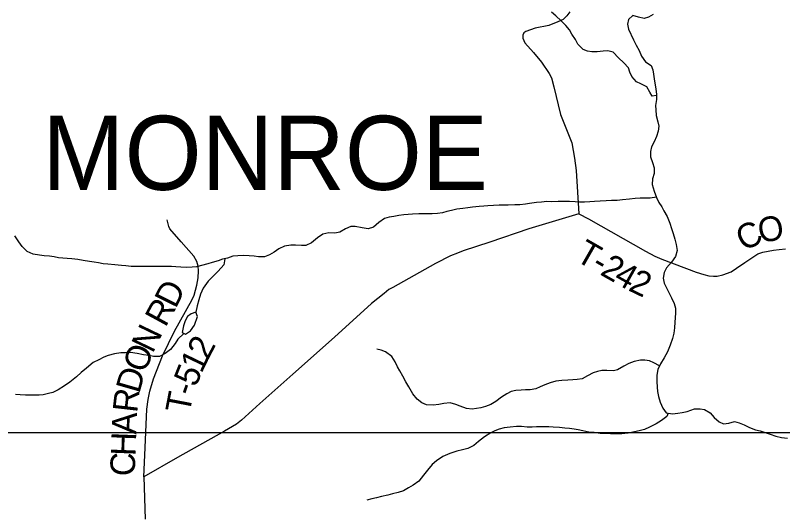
# Model space of a CAD drawing. Extents: x 1759416 to 2214760, y 252598 to 1116833.
# Drawn here: x 1993486 to 2002804, y 879430 to 885483 of the extents above; entities that cross this region are included whole.
import ezdxf

# ---------------------------------------------------------------- set-up
doc = ezdxf.new("R2010")
doc.units = 0
for name, color, linetype in [('GM_X_County_Road', 7, 'Continuous'), ('GM_X_Minor_Lake', 7, 'Continuous'), ('GM_X_Minor_River', 7, 'Continuous'), ('GM_X_Township_Road', 7, 'Continuous'), ('GM_X_Township_Road_Text', 7, 'Continuous'), ('GM_X_Township_Text', 7, 'Continuous'), ('SC_Scratch1', 7, 'Continuous')]:
    doc.layers.add(name, color=color, linetype=linetype)

msp = doc.modelspace()

# ---------------------------------------------------------------- linework, layer by layer
at = {"layer": 'GM_X_County_Road'}
msp.add_lwpolyline([(2000217.9, 885523.9), (2000183.9, 885475.9), (2000139.8, 885433.9), (2000073.7, 885403.9), (1999963.6, 885360), (1999797.5, 885326.1), (1999683.3, 885286.1), (1999661.3, 885270.1), (1999647.3, 885242.1), (1999647.2, 885206.1), (1999671.2, 885150), (1999779.1, 885031.7), (1999877, 884915.4), (1999969, 884777.1), (1999994.9, 884723.1), (2000026.8, 884612.9), (2000106.5, 884276.3), (2000242.6, 883936.1), (2000277.2, 883748.6), (2000296.4, 883600), (2000328.2, 883073), (1999721.7, 882889.1), (1999248.2, 882729.1), (1998923.9, 882623.2), (1998853.8, 882595.3), (1998769.7, 882561.3), (1998587.5, 882467.4), (1998070.8, 882175.5), (1998020.8, 882151.5), (1997964.7, 882105.5), (1997812.5, 881981.5), (1997359.7, 881573.4), (1996856.9, 881125.2), (1996454.3, 880767.2), (1996231.9, 880565.1), (1996169.8, 880519.1), (1996027.6, 880433.1), (1995456.9, 880113.3), (1995048.4, 879877.3), (1995061.1, 879363)], dxfattribs=at)
at = {"layer": 'GM_X_Minor_Lake'}
for points in [[(1995679.1, 881876.8), (1995622.9, 881857.1), (1995574.7, 881823.4), (1995550.3, 881771.5), (1995529.9, 881711.5), (1995513.4, 881629.5), (1995551.3, 881609.2), (1995611.6, 881648.9), (1995662.1, 881718.7), (1995698.8, 881824.6)], [(1995698.8, 881824.6), (1995679.1, 881876.8)]]:
    msp.add_lwpolyline(points, dxfattribs=at)
at = {"layer": 'GM_X_Minor_River'}
for points in [[(2001271.2, 884507.4), (2001219.1, 884499.7), (2001191.4, 884550), (2001155.7, 884612.3), (2001081.9, 884648.8), (2001030, 884673.2), (2000972.4, 884739.7), (2000948.7, 884793.9), (2000931, 884844.1), (2000873.3, 884906.6), (2000811.7, 884967.1), (2000746, 885035.6), (2000680.1, 885052), (2000624, 885046.4), (2000551.9, 885038.8), (2000487.8, 885039.2), (2000431.8, 885045.6), (2000379.9, 885068), (2000318.3, 885134.5), (2000286.6, 885188.8), (2000245, 885255.1), (2000213.3, 885307.4), (2000169.6, 885359.8), (2000115.9, 885416.2), (2000050.2, 885476.8), (1999998.4, 885521.2)], [(2001229.4, 885493.2), (2001175.1, 885459.5), (2001123, 885445.9), (2001053.1, 885462.3), (2000985.1, 885480.8), (2000930.7, 885433.1), (2000920.4, 885375), (2000930, 885314.9), (2000993.2, 885186.3), (2001024.9, 885121.9), (2001062.5, 885053.6), (2001090.1, 884985.3), (2001137.7, 884918.9), (2001205.5, 884874.4), (2001225.1, 884822.2), (2001236.8, 884768), (2001244.5, 884711.9), (2001250.1, 884659.8), (2001261.7, 884591.6), (2001271.3, 884519.4), (2001270.9, 884459.3), (2001258.4, 884387.3), (2001262.1, 884335.2), (2001267.6, 884267)], [(2001267.6, 884267), (2001287.2, 884188.8), (2001298.8, 884136.6), (2001292.5, 884076.5), (2001270, 884012.6), (2001243.6, 883944.6), (2001211.2, 883884.8), (2001196.8, 883830.8), (2001200.4, 883764.6), (2001222, 883696.4), (2001243.6, 883630.1), (2001243.1, 883560), (2001224.7, 883496), (2001220.3, 883427.9), (2001241.8, 883345.7), (2001273.3, 883271.4), (2001299, 883211.1), (2001334.7, 883158.8), (2001362.3, 883106.5), (2001402, 883038.2), (2001435.5, 882959.8), (2001455.1, 882895.6), (2001472.7, 882831.4), (2001494.3, 882763.1), (2001511.9, 882700.9), (2001523.4, 882626.7), (2001501, 882552.7), (2001452.5, 882482.9), (2001394, 882415.2), (2001365.6, 882361.3), (2001351.1, 882289.3), (2001362.8, 882231.1), (2001396.4, 882164.8), (2001426, 882106.5), (2001455.7, 882050.2), (2001487.3, 881981.9), (2001503, 881925.7), (2001502.6, 881869.6), (2001498.2, 881809.6), (2001495.9, 881755.5), (2001489.4, 881685.4), (2001481, 881621.4), (2001466.6, 881557.4), (2001438.1, 881477.4), (2001403.5, 881397.5), (2001363, 881323.7), (2001320.5, 881249.8), (2001286, 881179.9), (2001277.6, 881111.9), (2001275.1, 881035.8), (2001280.7, 880967.6), (2001284.3, 880913.5), (2001294, 880853.3), (2001317.5, 880785.1), (2001347.1, 880712.8), (2001390.8, 880656.4), (2001466.8, 880641.9), (2001530.9, 880649.5), (2001585, 880659.2), (2001643.1, 880672.8), (2001733.4, 880702.3), (2001801.5, 880703.9), (2001855.5, 880693.5), (2001923.3, 880653), (2001971, 880596.6), (2002030.7, 880546.1), (2002084.6, 880519.8), (2002150.7, 880529.3), (2002216.9, 880551), (2002276.8, 880532.5), (2002336.8, 880508.1), (2002402.6, 880475.7), (2002474.5, 880449.2), (2002530.5, 880434.8), (2002650.3, 880393.9), (2002720.2, 880371.5), (2002790.2, 880357), (2002864.2, 880346.5)], [(2001272.7, 883272.9), (2001195.2, 883261.8), (2001127.1, 883262.3), (2001075, 883260.6), (2001013, 883257), (2000944.9, 883249.4), (2000858.7, 883241.9), (2000792.6, 883234.4), (2000726.5, 883232.8), (2000658.5, 883229.2), (2000588.4, 883225.7), (2000520.3, 883220.1), (2000460.2, 883216.5), (2000398.1, 883214.8), (2000336.1, 883215.2), (2000282, 883215.6), (2000214, 883220), (2000147.9, 883222.5), (2000075.9, 883222.9), (2000001.8, 883219.4), (1999941.7, 883219.8), (1999875.6, 883214.2), (1999813.5, 883208.6), (1999731.4, 883197.1), (1999681.3, 883189.4), (1999613.2, 883181.8), (1999553.1, 883180.2), (1999471, 883176.7), (1999414.9, 883177.1), (1999360.9, 883175.4), (1999292.8, 883173.8), (1999224.7, 883170.3), (1999174.6, 883166.6), (1999116.6, 883162.9), (1999036.4, 883153.4), (1998982.3, 883145.8), (1998918.2, 883138.2), (1998846.1, 883126.6), (1998781.9, 883113), (1998725.8, 883101.3), (1998671.6, 883085.7), (1998611.5, 883076), (1998547.4, 883072.4), (1998459.4, 883071), (1998387.3, 883071.5), (1998307.2, 883068), (1998257.1, 883064.3), (1998205, 883058.6), (1998140.9, 883051), (1998080.8, 883041.4), (1998026.7, 883031.7), (1997968.5, 883016), (1997898.2, 882968.4), (1997833.7, 882910.7), (1997771.5, 882889.1), (1997695.6, 882901.6), (1997613.6, 882918.2), (1997559.5, 882916.5), (1997495.3, 882888.9), (1997427, 882847.2), (1997364.8, 882837.6), (1997294.8, 882842.1), (1997220.6, 882826.5), (1997154.3, 882780.9), (1997083.8, 882721.2), (1997015.5, 882685.6), (1996959.5, 882685.9), (1996887.4, 882690.4), (1996831.4, 882690.8), (1996753.2, 882679.2), (1996687, 882645.6), (1996628.7, 882605.9), (1996572.4, 882572.2), (1996512.2, 882550.6), (1996440.1, 882549), (1996388.1, 882557.4), (1996324.1, 882561.8), (1996256, 882564.2), (1996188, 882562.7), (1996127.9, 882557), (1996061.7, 882535.4), (1996003.5, 882519.8), (1995947.3, 882500.1), (1995877.2, 882480.5), (1995823, 882462.8), (1995686.6, 882429.7), (1995634.6, 882424), (1995562.5, 882418.4), (1995496.4, 882422.9), (1995436.4, 882427.2), (1995380.4, 882431.6), (1995324.3, 882434), (1995266.3, 882430.3), (1995208.2, 882430.7), (1995158.2, 882433), (1995092.1, 882431.4), (1994893.9, 882432.7), (1994825.9, 882439.2), (1994775.9, 882443.5), (1994693.8, 882452), (1994607.8, 882458.6)], [(1994607.8, 882458.6), (1994551.8, 882465), (1994497.8, 882475.3), (1994441.8, 882483.7), (1994387.8, 882492), (1994307.8, 882506.6), (1994243.8, 882517), (1994171.8, 882523.5), (1994115.8, 882527.8), (1994061.8, 882534.2), (1994011.7, 882538.5), (1993957.8, 882548.9), (1993899.8, 882557.3), (1993835.7, 882563.7), (1993777.7, 882570.1), (1993703.7, 882582.6), (1993629.9, 882613.1), (1993568.2, 882675.6), (1993528.5, 882729.9), (1993480.9, 882804.3)], [(1996028.4, 882526.5), (1996017.1, 882453.6), (1995950.6, 882375.9), (1995827.7, 882254.5), (1995765.1, 882170.7), (1995732.6, 882096.8), (1995716.1, 882028.8), (1995695.6, 881952.8), (1995679.1, 881876.8)], [(1995533, 881619), (1995460.8, 881547.7), (1995426.5, 881495.8), (1995370, 881424), (1995305.6, 881376.4), (1995237.3, 881338.8), (1995165.2, 881339.2), (1995111.2, 881349.6), (1995041.2, 881360), (1994965.3, 881374.6), (1994883.3, 881387.1), (1994825.2, 881385.5), (1994765.1, 881381.8), (1994691, 881370.3), (1994612.8, 881350.8), (1994562.6, 881329.1), (1994500.3, 881299.4), (1994432.1, 881265.8), (1994351.5, 881196.2), (1994287.2, 881146.5), (1994226.8, 881090.8), (1994148.3, 881029.2), (1994083.9, 880981.5), (1994007.6, 880936), (1993941.3, 880902.3), (1993889.1, 880888.6), (1993825, 880875), (1993774.9, 880871.3), (1993718.9, 880869.7), (1993662.8, 880870.1), (1993610.8, 880870.4), (1993544.7, 880874.8), (1993488.7, 880877.2)], [(2001308.4, 881225.3), (2001240.5, 881262.3), (2001188.6, 881286.7), (2001130.6, 881295.1), (2001076.5, 881293.4), (2001000.4, 881277.9), (2000936.1, 881252.3), (2000873.9, 881220.6), (2000799.5, 881179), (2000749.4, 881165.3), (2000669.4, 881167.8), (2000609.3, 881170.2), (2000553.2, 881156.6), (2000503, 881138.8), (2000434.7, 881103.2), (2000368.5, 881069.6), (2000310.3, 881057.9), (2000254.2, 881054.3), (2000194.2, 881050.7), (2000122.1, 881049.1), (2000048, 881039.6), (1999979.8, 881020), (1999915.5, 880994.4), (1999859.3, 880970.7), (1999807.1, 880945), (1999737, 880933.4), (1999682.9, 880933.8), (1999628.9, 880930.1), (1999564.8, 880926.5), (1999508.6, 880912.8), (1999454.4, 880885.1), (1999390.1, 880845.5), (1999321.7, 880791.8), (1999261.4, 880758.2), (1999193.2, 880730.5), (1999139, 880716.9), (1999086.9, 880707.2), (1999032.8, 880701.5), (1998964.8, 880706), (1998888.9, 880734.5), (1998835, 880756.9), (1998767.1, 880775.3), (1998688.9, 880767.8), (1998628.8, 880756.2), (1998558.7, 880748.6), (1998480.6, 880753.1), (1998422.7, 880775.5), (1998365, 880822), (1998311.3, 880884.4), (1998263.8, 880968.9), (1998226.2, 881033.2), (1998190.6, 881101.5), (1998156.9, 881163.9), (1998127.2, 881214.1), (1998097.6, 881274.4), (1998056, 881340.8), (1997982.3, 881397.3), (1997926.3, 881415.7), (1997874.4, 881430.1)], [(2001412.7, 880652.2), (2001398.5, 880610.3), (2001332.1, 880562.6), (2001267.8, 880523), (2001187.5, 880479.4), (2001125.3, 880453.8), (2001063.1, 880436.2), (2001004.9, 880422.5), (2000926.8, 880407), (2000850.7, 880401.4), (2000764.6, 880400), (2000714.5, 880398.3), (2000644.5, 880402.8), (2000588.4, 880405.1), (2000514.4, 880415.6), (2000450.4, 880422), (2000378.4, 880436.5), (2000322.4, 880446.9), (2000270.4, 880455.2), (2000216.5, 880463.6), (2000160.4, 880470), (2000092.4, 880478.4), (2000018.4, 880482.9), (1999964.3, 880483.2), (1999886.3, 880485.7), (1999816.2, 880484.2), (1999760.1, 880480.5), (1999702.1, 880478.9), (1999632, 880487.3), (1999572, 880487.7), (1999495.9, 880482.2), (1999423.8, 880472.7), (1999359.6, 880455), (1999309.4, 880437.3), (1999259.2, 880411.6), (1999182.8, 880362), (1999110.4, 880308.4), (1999052, 880256.7), (1998981.7, 880221.1), (1998917.6, 880207.5), (1998845.4, 880187.9), (1998763.1, 880160.4), (1998676.8, 880122.9), (1998600.4, 880073.3), (1998548.1, 880025.5), (1998491.6, 879957.8), (1998443.2, 879898), (1998386.7, 879826.2), (1998318.3, 879776.6), (1998262, 879744.9), (1998197.7, 879709.3), (1998133.5, 879687.6), (1998067.4, 879672), (1998009.2, 879654.4), (1997933, 879638.8), (1997872.9, 879623.2), (1997816.7, 879609.5), (1997752.6, 879595.9)]]:
    msp.add_lwpolyline(points, dxfattribs=at)
at = {"layer": 'GM_X_Township_Road'}
for points in [[(2000328.2, 883073), (2000446.7, 883011.2), (2001136.3, 882616.8), (2001251.2, 882558.5), (2001336.2, 882519.6), (2001753, 882361.8), (2001844.5, 882333.9), (2001907.9, 882320.2), (2001964, 882314.4), (2002008.1, 882313.9), (2002075.3, 882331.2), (2002177, 882369.2), (2002243.3, 882413.5), (2002342.3, 882482.4), (2002452.2, 882552.8), (2002501.5, 882584.1), (2002562.5, 882604.4), (2002690.7, 882630.1), (2002761.4, 882638.9), (2002836.6, 882647.8)], [(1995048.4, 879877.3), (1995058.7, 880139.7), (1995083.3, 880700.4), (1995097.5, 880816.5), (1995117.6, 880916.7), (1995163.8, 881068.8), (1995272.2, 881349.1), (1995420.6, 881647.4), (1995629.2, 882021.7), (1995657.3, 882085.7), (1995691.4, 882203.8), (1995707.5, 882293.9), (1995711.6, 882380.1), (1995705.7, 882436.1), (1995689.7, 882494.2), (1995651.8, 882558.4), (1995499.9, 882730.7), (1995362, 882891.1), (1995348, 882917.2), (1995330.1, 882997.3)]]:
    msp.add_lwpolyline(points, dxfattribs=at)
at = {"layer": 'SC_Scratch1'}
msp.add_lwpolyline([(1984253.2, 880416.3), (2020157.2, 880416.3), (2020157.2, 844512.3), (1984253.2, 844512.3)], close=True, dxfattribs=at)

# ---------------------------------------------------------------- texts
at = {"layer": 'GM_X_Township_Road_Text'}
for s, rotation, p in [('O', 9.79169, (2002529.5, 882716.3)), ('C', 27.14104, (2002332.9, 882611.5)), ('T', 330.21154, (2000272.4, 882512.9)), ('2', 330.31119, (2000574.6, 882340)), ('-', 330.23208, (2000467.3, 882401.4)), ('4', 330.64344, (2000736.8, 882247.6)), ('2', 334.37935, (2000916.8, 882147.1)), ('D', 63.50919, (1995432.3, 881911)), ('R', 61.46741, (1995309.2, 881684.2)), ('N', 64.287, (1995154.3, 881367.5)), ('2', 62.61808, (1995824.5, 881288.5)), ('O', 68.58483, (1995060.3, 881127.2)), ('1', 64.27979, (1995745.3, 881124.1)), ('5', 68.19279, (1995678.9, 880957.5)), ('D', 73.98605, (1994989.9, 880880.5)), ('-', 70.94792, (1995640, 880844.6)), ('R', 83.49947, (1994964.6, 880648.6)), ('T', 79.10864, (1995600.5, 880635.1)), ('A', 87.67167, (1994954.3, 880390.6)), ('H', 87.84197, (1994944.3, 880127)), ('C', 87.84119, (1994935.1, 879880.8))]:
    msp.add_text(s, height=300, rotation=rotation, dxfattribs=at).set_placement(p)
at = {"layer": 'GM_X_Township_Text'}
msp.add_text('MONROE', height=900, rotation=0.00001, dxfattribs=at).set_placement((1993810.3, 883362.9))

doc.saveas('drawing.dxf')
